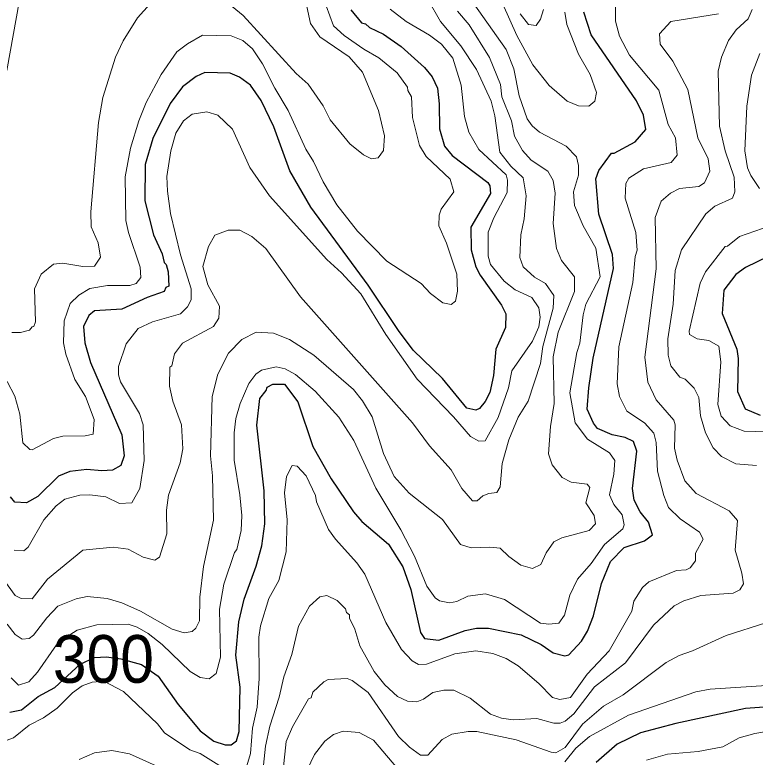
# Model space of a CAD drawing. Extents: x 673.3 to 698.5, y 6984.3 to 7012.3.
# Drawn here: x 687.627 to 688.869, y 6986.54 to 6987.786 of the extents above; entities that cross this region are included whole.
import ezdxf
from ezdxf.enums import TextEntityAlignment as Align

# ---------------------------------------------------------------- set-up
doc = ezdxf.new("R2010")
doc.units = 0
doc.header["$LTSCALE"] = 0.032
doc.layers.add('1', color=7, linetype='Continuous', lineweight=25)
doc.layers.add('2', color=7, linetype='Continuous', lineweight=13)
doc.layers.add('61', color=7, linetype='Continuous')

msp = doc.modelspace()

# ---------------------------------------------------------------- linework, layer by layer
at = {"layer": '1'}
for points in [[(688.1903, 6987.794), (688.2086, 6987.7726), (688.2153, 6987.7709), (688.2217, 6987.7647), (688.2455, 6987.7531), (688.2751, 6987.7325), (688.3143, 6987.6971), (688.3272, 6987.6818), (688.336, 6987.6625), (688.3389, 6987.6365), (688.3393, 6987.5944), (688.3478, 6987.5653), (688.3607, 6987.5499), (688.4207, 6987.5043), (688.4238, 6987.4986), (688.4252, 6987.4857), (688.3918, 6987.4293), (688.3926, 6987.3911), (688.4004, 6987.3627)], [(688.1014, 6987.1361), (688.1266, 6987.0612), (688.1577, 6987.0072), (688.1949, 6986.9515), (688.2088, 6986.9354), (688.2535, 6986.8971), (688.2781, 6986.8592), (688.2915, 6986.8211), (688.3076, 6986.7489), (688.3143, 6986.7388), (688.338, 6986.7362), (688.3823, 6986.7525), (688.4013, 6986.7564), (688.4214, 6986.7564), (688.4762, 6986.7451), (688.5101, 6986.7292), (688.5304, 6986.715), (688.5495, 6986.7101), (688.5564, 6986.7116), (688.5777, 6986.7346), (688.588, 6986.7513), (688.5979, 6986.7771), (688.6112, 6986.8312), (688.6264, 6986.868), (688.6492, 6986.8916), (688.6834, 6986.9031), (688.697, 6986.913), (688.6903, 6986.9345), (688.6764, 6986.9518), (688.6662, 6986.9714), (688.6631, 6986.991), (688.6704, 6987.0537), (688.6647, 6987.0696), (688.6511, 6987.0764), (688.6289, 6987.0809), (688.6044, 6987.0912), (688.5977, 6987.1004), (688.5873, 6987.124), (688.5897, 6987.1596), (688.5971, 6987.2096), (688.6312, 6987.3599), (688.6296, 6987.3836), (688.6068, 6987.4514), (688.602, 6987.5106), (688.607, 6987.5247), (688.628, 6987.5536), (688.6325, 6987.5538), (688.6678, 6987.5725), (688.6858, 6987.5931), (688.6818, 6987.6174), (688.6697, 6987.6414), (688.594, 6987.7522), (688.5816, 6987.7902)], [(688.4004, 6987.3627), (688.4075, 6987.3488), (688.4435, 6987.2987), (688.4509, 6987.284), (688.4503, 6987.2611), (688.4341, 6987.2245), (688.4301, 6987.1807), (688.4237, 6987.1517), (688.4162, 6987.1369), (688.4063, 6987.1252), (688.4006, 6987.1222), (688.3854, 6987.1254), (688.3443, 6987.1753), (688.295, 6987.223), (688.2705, 6987.2557), (688.2199, 6987.332), (688.1233, 6987.4631), (688.0882, 6987.5242), (688.0612, 6987.5977), (688.0399, 6987.642), (688.0221, 6987.6677), (688.0038, 6987.6813), (687.9879, 6987.6881), (687.9453, 6987.6888), (687.931, 6987.6824), (687.908, 6987.6651), (687.8871, 6987.6371), (687.8585, 6987.5784), (687.8455, 6987.5345), (687.8446, 6987.4736), (687.8596, 6987.4165), (687.8738, 6987.3846), (687.8771, 6987.3701), (687.8806, 6987.3666), (687.8838, 6987.3544), (687.8853, 6987.3303), (687.8803, 6987.3279), (687.8772, 6987.3214), (687.8488, 6987.3116), (687.8063, 6987.2916), (687.7601, 6987.289), (687.751, 6987.2809), (687.742, 6987.2626), (687.7444, 6987.2352), (687.7538, 6987.2023), (687.8064, 6987.0811), (687.8104, 6987.0456), (687.8047, 6987.0295), (687.7904, 6987.0217), (687.7728, 6987.0203), (687.7473, 6987.0227), (687.7191, 6987.0195), (687.6997, 6987.0113), (687.665, 6986.9776), (687.6465, 6986.9669), (687.6268, 6986.9681), (687.6194, 6986.9768)], [(688.9095, 6987.389), (688.8531, 6987.3617), (688.8364, 6987.35), (688.8168, 6987.3239), (688.8137, 6987.2845), (688.8382, 6987.2244), (688.8405, 6987.2087), (688.8396, 6987.1537), (688.8524, 6987.1244), (688.8773, 6987.114)], [(687.6184, 6986.6156), (687.6381, 6986.6192), (687.6657, 6986.6418), (687.6937, 6986.657), (687.7363, 6986.6961), (687.7604, 6986.7071), (687.7806, 6986.708), (687.8045, 6986.7047), (687.8394, 6986.6953), (687.8673, 6986.6758), (687.9006, 6986.628), (687.9379, 6986.5841), (687.9604, 6986.5666), (687.9795, 6986.5603), (687.9895, 6986.5608), (687.9985, 6986.567), (688.0034, 6986.5831), (688.005, 6986.6571), (687.9977, 6986.7109), (688.0025, 6986.7667), (688.0118, 6986.8052), (688.0319, 6986.8602), (688.0413, 6986.8944), (688.0465, 6986.9312), (688.0451, 6986.9871), (688.0329, 6987.097), (688.0379, 6987.1419), (688.0487, 6987.1554), (688.05, 6987.1611), (688.0598, 6987.1661), (688.0791, 6987.166), (688.1014, 6987.1361)], [(688.9306, 6986.6269), (688.8528, 6986.6213), (688.7358, 6986.5961), (688.6765, 6986.5804), (688.6376, 6986.5616), (688.6025, 6986.5306)]]:
    msp.add_lwpolyline(points, dxfattribs=at)
at = {"layer": '2'}
for points in [[(688.5645, 6987.4889), (688.5726, 6987.5164), (688.5726, 6987.5328), (688.5694, 6987.5475), (688.5522, 6987.5651), (688.5074, 6987.5887), (688.4949, 6987.5997), (688.4867, 6987.611), (688.4733, 6987.6499), (688.4643, 6987.6951), (688.4513, 6987.7278), (688.373, 6987.839)], [(687.6344, 6987.8112), (687.6132, 6987.6923)], [(687.6215, 6987.2525), (687.6364, 6987.2525), (687.6512, 6987.2564), (687.6556, 6987.262), (687.6587, 6987.2624), (687.6614, 6987.2704), (687.6597, 6987.326), (687.6707, 6987.3505), (687.6915, 6987.3671), (687.7073, 6987.3689), (687.7407, 6987.3635), (687.7604, 6987.364), (687.7704, 6987.3789), (687.7665, 6987.4033), (687.755, 6987.4297), (687.7542, 6987.4554), (687.7672, 6987.6048), (687.7746, 6987.6469), (687.7956, 6987.7148), (687.8084, 6987.7422), (687.8323, 6987.7809), (687.8595, 6987.8104)], [(687.6558, 6986.8056), (687.6814, 6986.8385), (687.7406, 6986.8875), (687.7915, 6986.8924), (687.8166, 6986.8892), (687.8423, 6986.8756), (687.8615, 6986.8706), (687.8697, 6986.8753), (687.882, 6986.9149), (687.8812, 6986.9543), (687.8843, 6986.9798), (687.9044, 6987.0337), (687.9088, 6987.0574), (687.9064, 6987.0977), (687.8917, 6987.1371), (687.8861, 6987.1626), (687.887, 6987.1942), (687.8901, 6987.1965), (687.8945, 6987.2166), (687.9083, 6987.2347), (687.9599, 6987.2628), (687.969, 6987.2769), (687.9699, 6987.2969), (687.9503, 6987.3325), (687.9423, 6987.3634), (687.9518, 6987.3968), (687.9625, 6987.4159), (687.9846, 6987.4242), (688.0045, 6987.4241), (688.0243, 6987.414), (688.048, 6987.3934), (688.1061, 6987.3125), (688.2942, 6987.1007), (688.3224, 6987.0621), (688.3592, 6987.0222), (688.3767, 6986.9909), (688.3945, 6986.9703), (688.4024, 6986.97), (688.4122, 6986.9787), (688.4222, 6986.9826), (688.4357, 6986.9838), (688.4414, 6986.9935), (688.4448, 6987.0328), (688.4556, 6987.0723), (688.4715, 6987.1104), (688.4882, 6987.1375), (688.5087, 6987.2008), (688.5126, 6987.2292), (688.5302, 6987.2932), (688.531, 6987.3149), (688.5171, 6987.3346), (688.4987, 6987.3452), (688.4797, 6987.3627), (688.4741, 6987.3782), (688.4756, 6987.4166), (688.4814, 6987.4431), (688.4846, 6987.4821), (688.4797, 6987.512), (688.459, 6987.532), (688.4407, 6987.5554), (688.4324, 6987.6163), (688.4262, 6987.6411), (688.4014, 6987.6941), (688.3751, 6987.7335), (688.341, 6987.7746), (688.319, 6987.8132)], [(687.973, 6987.8153), (688.0101, 6987.7847), (688.0989, 6987.6871), (688.119, 6987.6694), (688.1441, 6987.6329), (688.1561, 6987.6098), (688.1888, 6987.5693), (688.212, 6987.5506), (688.2251, 6987.544), (688.2364, 6987.5457), (688.2452, 6987.5582), (688.2468, 6987.5828), (688.237, 6987.6254), (688.2099, 6987.6895), (688.1875, 6987.715), (688.1385, 6987.7491), (688.1228, 6987.771), (688.1169, 6987.8)], [(688.6346, 6987.8064), (688.6346, 6987.7753), (688.6412, 6987.7498), (688.6583, 6987.718)], [(687.6138, 6987.1702), (687.6269, 6987.1455), (687.6353, 6987.1154), (687.6402, 6987.0673), (687.6518, 6987.0561), (687.6556, 6987.0555), (687.6914, 6987.0748), (687.7071, 6987.0788), (687.7446, 6987.079), (687.7581, 6987.0822), (687.7598, 6987.1063), (687.7451, 6987.1452), (687.7275, 6987.1737), (687.712, 6987.216), (687.7086, 6987.2355), (687.7094, 6987.2722), (687.7193, 6987.3013), (687.734, 6987.3153), (687.7528, 6987.3262), (687.7821, 6987.3313), (687.8198, 6987.3314), (687.8305, 6987.3347), (687.838, 6987.345), (687.8372, 6987.362), (687.8173, 6987.4202), (687.8128, 6987.4407), (687.812, 6987.5136), (687.8209, 6987.5619), (687.8349, 6987.6081), (687.8472, 6987.6385), (687.8722, 6987.6856), (687.8988, 6987.7236), (687.9167, 6987.7373), (687.9418, 6987.7516), (687.9895, 6987.7508), (688.0091, 6987.7426), (688.0255, 6987.7286), (688.0424, 6987.7035), (688.063, 6987.6626), (688.0856, 6987.6254), (688.1148, 6987.5605), (688.1278, 6987.5394), (688.1439, 6987.5055), (688.1672, 6987.4667), (688.2015, 6987.4228), (688.2507, 6987.3725), (688.3085, 6987.3348), (688.3245, 6987.3181), (688.3448, 6987.3022), (688.359, 6987.2997), (688.3664, 6987.3054), (688.3698, 6987.3222), (688.3682, 6987.3504), (688.3509, 6987.4025), (688.3381, 6987.4317), (688.3389, 6987.4495), (688.3424, 6987.4598), (688.3633, 6987.4888), (688.3571, 6987.5099), (688.3171, 6987.5479), (688.3056, 6987.5664), (688.2941, 6987.6134), (688.2924, 6987.6482), (688.286, 6987.6589), (688.2858, 6987.6645), (688.2682, 6987.6887), (688.2377, 6987.7135), (688.2121, 6987.7279), (688.1791, 6987.7513), (688.1617, 6987.7671), (688.1493, 6987.8007)], [(688.2564, 6987.7951), (688.2837, 6987.7746), (688.3227, 6987.7515), (688.3427, 6987.7363), (688.3616, 6987.7133), (688.3755, 6987.6677), (688.3813, 6987.615), (688.3888, 6987.589), (688.4055, 6987.5595), (688.4514, 6987.5173), (688.4537, 6987.5081), (688.4527, 6987.4877), (688.4304, 6987.4452), (688.4213, 6987.4208), (688.4208, 6987.3805), (688.4251, 6987.3668), (688.4477, 6987.3385), (688.4661, 6987.3242), (688.4945, 6987.3116), (688.506, 6987.2942), (688.5082, 6987.2783), (688.5058, 6987.2623), (688.4954, 6987.238), (688.4609, 6987.1881), (688.4553, 6987.1597), (688.4378, 6987.1101), (688.4161, 6987.0709), (688.4051, 6987.07), (688.3912, 6987.078), (688.3629, 6987.1111), (688.3018, 6987.174), (688.2493, 6987.2491), (688.2071, 6987.3173), (688.1748, 6987.3529), (688.1504, 6987.3749), (688.054, 6987.4819), (688.0212, 6987.5296), (687.992, 6987.5937), (687.9672, 6987.6173), (687.9491, 6987.6228), (687.9244, 6987.6188), (687.9096, 6987.6081), (687.8971, 6987.5874), (687.8883, 6987.5576), (687.882, 6987.5143), (687.8827, 6987.4896), (687.8878, 6987.4525), (687.9048, 6987.3828), (687.9227, 6987.3257), (687.9227, 6987.3073), (687.9164, 6987.2956), (687.9047, 6987.2837), (687.8578, 6987.2703), (687.8336, 6987.2594), (687.8135, 6987.2335)], [(688.4458, 6987.8034), (688.469, 6987.751), (688.4962, 6987.7017), (688.5233, 6987.6673), (688.5534, 6987.641), (688.5724, 6987.6332), (688.5899, 6987.6323), (688.6003, 6987.6409), (688.6027, 6987.6552), (688.592, 6987.6859), (688.5726, 6987.7198), (688.5532, 6987.7697), (688.5498, 6987.7903)], [(688.5139, 6987.7946), (688.5091, 6987.7787), (688.5017, 6987.7678), (688.4887, 6987.7697), (688.4747, 6987.7877)], [(688.8641, 6987.7946), (688.8575, 6987.7792), (688.8373, 6987.7605), (688.8243, 6987.7426), (688.8128, 6987.7148), (688.8072, 6987.6915), (688.8094, 6987.5987), (688.819, 6987.5573), (688.834, 6987.5133), (688.835, 6987.4885), (688.8312, 6987.4779), (688.8012, 6987.4644), (688.7861, 6987.452), (688.7454, 6987.3911), (688.7347, 6987.3569), (688.7315, 6987.2999), (688.7225, 6987.242), (688.7233, 6987.2143), (688.7275, 6987.1968), (688.7428, 6987.1777), (688.7519, 6987.1742), (688.7667, 6987.1591), (688.7744, 6987.1436), (688.7775, 6987.1128), (688.7857, 6987.0844), (688.7987, 6987.0591), (688.8125, 6987.0444), (688.8367, 6987.0322), (688.8713, 6987.0293)], [(688.1029, 6986.7595), (688.1214, 6986.7931), (688.1386, 6986.8092), (688.1504, 6986.8111), (688.1679, 6986.8029), (688.1816, 6986.789), (688.1834, 6986.7827), (688.1882, 6986.779), (688.1883, 6986.773), (688.1975, 6986.7546), (688.2059, 6986.7269), (688.2296, 6986.6838), (688.2478, 6986.661), (688.2691, 6986.6418), (688.2859, 6986.6338), (688.3013, 6986.6325), (688.3124, 6986.637), (688.3281, 6986.6482), (688.3468, 6986.6523), (688.3635, 6986.6523), (688.391, 6986.6389), (688.4247, 6986.6122), (688.4433, 6986.6051), (688.4629, 6986.6026), (688.5026, 6986.6049), (688.5313, 6986.597), (688.5421, 6986.5969), (688.5503, 6986.6004), (688.5648, 6986.6128), (688.5997, 6986.6581), (688.6513, 6986.6983), (688.6984, 6986.7616), (688.7332, 6986.794), (688.7496, 6986.8021), (688.7778, 6986.811), (688.8323, 6986.8149), (688.8434, 6986.8206), (688.8494, 6986.8305), (688.847, 6986.8488), (688.8357, 6986.8874), (688.8397, 6986.9369), (688.8253, 6986.9531), (688.7702, 6986.9825), (688.7509, 6987.0036), (688.7381, 6987.0384), (688.7339, 6987.0584), (688.7346, 6987.0977), (688.7324, 6987.1053), (688.7027, 6987.1396), (688.6891, 6987.1694), (688.6842, 6987.2111), (688.7029, 6987.3593), (688.7013, 6987.4454), (688.7111, 6987.473), (688.727, 6987.4864), (688.742, 6987.4942), (688.7746, 6987.4974), (688.7842, 6987.5039), (688.7933, 6987.5233), (688.79, 6987.5439), (688.773, 6987.5792), (688.7564, 6987.6602), (688.731, 6987.7079), (688.7095, 6987.7364), (688.7087, 6987.7541), (688.7276, 6987.7744), (688.8074, 6987.7876)], [(688.3695, 6987.792), (688.3892, 6987.769), (688.4233, 6987.7139), (688.442, 6987.6687), (688.444, 6987.648), (688.46, 6987.6081), (688.4652, 6987.5823), (688.4787, 6987.5578), (688.4931, 6987.542), (688.5212, 6987.5235), (688.5302, 6987.5078), (688.5336, 6987.4863), (688.5303, 6987.4355), (688.5357, 6987.3935), (688.544, 6987.3734), (688.5658, 6987.3462), (688.5657, 6987.3215), (688.5386, 6987.253), (688.5303, 6987.212), (688.5318, 6987.1335), (688.5254, 6987.095), (688.5225, 6987.0492), (688.5284, 6987.0305), (688.545, 6987.0095), (688.5602, 6987.0015), (688.587, 6986.9983), (688.5918, 6986.9923), (688.5849, 6986.9667), (688.5992, 6986.9457), (688.6009, 6986.9314), (688.5908, 6986.9205), (688.5444, 6986.9079), (688.5312, 6986.9014), (688.5181, 6986.8826), (688.5097, 6986.863), (688.4952, 6986.8567), (688.4758, 6986.862), (688.4557, 6986.8765), (688.4412, 6986.8908), (688.4237, 6986.8925), (688.3926, 6986.8909), (688.3747, 6986.8969), (688.3445, 6986.9388), (688.2887, 6986.9829), (688.2633, 6987.0111), (688.2456, 6987.0496), (688.2263, 6987.111), (688.2103, 6987.1379), (688.1951, 6987.1568)], [(688.6583, 6987.718), (688.7074, 6987.6592), (688.7232, 6987.6016), (688.7356, 6987.5792), (688.7385, 6987.5504), (688.7284, 6987.5378), (688.6815, 6987.5275), (688.6572, 6987.5117), (688.652, 6987.5024), (688.6508, 6987.4782), (688.6687, 6987.4202), (688.671, 6987.3906), (688.6677, 6987.3801), (688.6637, 6987.3366), (688.6403, 6987.2286), (688.6373, 6987.1665), (688.6417, 6987.1452), (688.6539, 6987.1207), (688.6832, 6987.1011), (688.6992, 6987.0837), (688.703, 6987.0681), (688.7053, 6987.0198), (688.7156, 6986.9791), (688.7237, 6986.959), (688.7434, 6986.9398), (688.7758, 6986.9172), (688.782, 6986.9055), (688.7689, 6986.8823), (688.7688, 6986.8692), (688.76, 6986.8575), (688.7534, 6986.8542), (688.7372, 6986.8533), (688.6905, 6986.8341), (688.6802, 6986.8247), (688.6656, 6986.8015), (688.662, 6986.7847), (688.6239, 6986.7183), (688.587, 6986.6792), (688.5592, 6986.6397), (688.5415, 6986.6368), (688.5289, 6986.64), (688.5058, 6986.6636), (688.4714, 6986.6931), (688.451, 6986.7053), (688.4291, 6986.7141), (688.4006, 6986.7181), (688.3651, 6986.7133), (688.3175, 6986.696), (688.3041, 6986.6954), (688.2936, 6986.7017), (688.2755, 6986.7207), (688.2492, 6986.7657), (688.2141, 6986.8471), (688.2006, 6986.8662), (688.1646, 6986.9055), (688.1532, 6986.9218), (688.1331, 6986.9685), (688.1311, 6986.9791), (688.1155, 6987.0122), (688.1007, 6987.028), (688.0923, 6987.0291), (688.0826, 6987.0108), (688.0791, 6986.9837), (688.0839, 6986.9383), (688.0823, 6986.8843), (688.0697, 6986.8364), (688.0532, 6986.8064), (688.0391, 6986.7603), (688.036, 6986.7413), (688.0368, 6986.6716), (688.0334, 6986.6238), (688.0254, 6986.5885), (688.022, 6986.5458), (688.0159, 6986.5252)], [(688.8763, 6987.4941), (688.8617, 6987.5161), (688.8565, 6987.5287), (688.852, 6987.5577), (688.8553, 6987.6322), (688.8631, 6987.6847), (688.877, 6987.7209)], [(687.6203, 6986.6732), (687.6329, 6986.6605), (687.6501, 6986.6663), (687.6649, 6986.6826), (687.6968, 6986.7284), (687.7067, 6986.7375), (687.7311, 6986.753), (687.7641, 6986.7621), (687.8169, 6986.7629), (687.8321, 6986.7578), (687.8503, 6986.7475), (687.874, 6986.729), (687.9211, 6986.6834), (687.9377, 6986.6733), (687.953, 6986.6712), (687.9644, 6986.6803), (687.9716, 6986.7079), (687.97, 6986.7885), (687.9776, 6986.8303), (687.9952, 6986.8833), (687.9994, 6986.8882), (688.0067, 6986.9204), (688.0074, 6986.9452), (688.0042, 6986.9802), (687.9945, 6987.0384), (687.9945, 6987.084), (687.9977, 6987.108), (688.0048, 6987.1332), (688.0193, 6987.1672), (688.0314, 6987.1828), (688.0404, 6987.1896), (688.065, 6987.1952), (688.0805, 6987.1914), (688.0978, 6987.1821), (688.1309, 6987.1542), (688.1705, 6987.1105), (688.1958, 6987.0711), (688.2323, 6986.9916), (688.2744, 6986.9212), (688.2976, 6986.8773), (688.3182, 6986.8271), (688.3323, 6986.807), (688.3391, 6986.802), (688.356, 6986.7989), (688.3686, 6986.8013), (688.3868, 6986.8101), (688.4163, 6986.8142), (688.4483, 6986.8047), (688.5091, 6986.7647), (688.5231, 6986.763), (688.5399, 6986.7646), (688.5494, 6986.7781), (688.5583, 6986.8119), (688.5709, 6986.8385), (688.5939, 6986.8651), (688.6161, 6986.8969), (688.6468, 6986.923), (688.6491, 6986.9299), (688.646, 6986.9465), (688.6321, 6986.9639), (688.6248, 6986.9802), (688.6321, 6987.0149), (688.6336, 6987.0379), (688.6247, 6987.0505), (688.5877, 6987.0737), (688.567, 6987.1007), (688.558, 6987.1512), (688.5697, 6987.2188), (688.5751, 6987.2348), (688.5806, 6987.2824), (688.5849, 6987.2999), (688.6091, 6987.3462), (688.6018, 6987.3944), (688.5806, 6987.4319), (688.5657, 6987.4655), (688.5645, 6987.4889)], [(688.9087, 6987.0855), (688.8505, 6987.0871), (688.8271, 6987.0959), (688.8121, 6987.1123), (688.8064, 6987.1317), (688.8113, 6987.2031), (688.8081, 6987.2297), (688.7915, 6987.2391), (688.7716, 6987.2418), (688.7592, 6987.2492), (688.7584, 6987.2549), (688.7769, 6987.3352), (688.7856, 6987.3545), (688.8185, 6987.3971), (688.8226, 6987.3975), (688.8428, 6987.4135), (688.8941, 6987.4318)], [(688.1951, 6987.1568), (688.1282, 6987.2147), (688.0875, 6987.2409), (688.061, 6987.2515), (688.0319, 6987.2532), (688.0079, 6987.2407), (687.9853, 6987.218), (687.9674, 6987.1826), (687.9581, 6987.145), (687.9553, 6987.0456), (687.9585, 6987.0119), (687.9601, 6986.9375), (687.9431, 6986.8599), (687.9374, 6986.8086), (687.9365, 6986.7687), (687.9306, 6986.7562), (687.9242, 6986.7506), (687.911, 6986.7487), (687.8908, 6986.7547), (687.8377, 6986.785), (687.8063, 6986.799), (687.7818, 6986.8061), (687.748, 6986.8093), (687.7295, 6986.8055), (687.6989, 6986.7931), (687.6802, 6986.7737), (687.6581, 6986.7444), (687.651, 6986.7391), (687.6389, 6986.7379), (687.6271, 6986.7459), (687.6138, 6986.763)], [(687.8135, 6987.2335), (687.8006, 6987.1957), (687.8006, 6987.1816), (687.8038, 6987.1696), (687.8359, 6987.1167), (687.8421, 6987.0977), (687.8438, 6987.0377), (687.8362, 6986.9909), (687.8233, 6986.9666), (687.8025, 6986.9658), (687.7796, 6986.9765), (687.7523, 6986.9804), (687.7357, 6986.9796), (687.7108, 6986.9728), (687.6963, 6986.9616), (687.6753, 6986.9382), (687.6491, 6986.8925), (687.6416, 6986.886), (687.6256, 6986.887)], [(687.586, 6986.8675), (687.627, 6986.8112), (687.6373, 6986.8062), (687.6558, 6986.8056)], [(688.0414, 6986.4997), (688.0473, 6986.5585), (688.0544, 6986.5918), (688.0702, 6986.6403), (688.078, 6986.6749), (688.0914, 6986.7119), (688.1029, 6986.7595)], [(688.8868, 6986.7654), (688.8202, 6986.7442), (688.7642, 6986.7183), (688.7418, 6986.7107), (688.7195, 6986.6988), (688.6475, 6986.6446), (688.6148, 6986.6252), (688.5795, 6986.595), (688.55, 6986.5562), (688.5347, 6986.5472), (688.5268, 6986.548), (688.4681, 6986.5692), (688.4022, 6986.5828), (688.3873, 6986.583), (688.36, 6986.5785), (688.3441, 6986.5695), (688.3198, 6986.5434), (688.3072, 6986.5431), (688.2889, 6986.5565), (688.2704, 6986.5743), (688.2195, 6986.6485), (688.1926, 6986.6687), (688.1844, 6986.6718), (688.1525, 6986.6701), (688.1451, 6986.6665), (688.1267, 6986.6492), (688.124, 6986.6394), (688.1196, 6986.6378), (688.0926, 6986.5906), (688.0823, 6986.5664), (688.0709, 6986.4603)], [(687.9827, 6986.5178), (687.9377, 6986.5462), (687.9206, 6986.5523), (687.8776, 6986.5808), (687.8659, 6986.5958), (687.8092, 6986.6502), (687.776, 6986.6672), (687.7565, 6986.6657), (687.7396, 6986.6596), (687.7235, 6986.6479), (687.6979, 6986.6223), (687.6746, 6986.6059), (687.6507, 6986.5935), (687.6245, 6986.5722), (687.5963, 6986.562), (687.5854, 6986.5705), (687.5679, 6986.6362), (687.5538, 6986.6523), (687.5397, 6986.6636), (687.5067, 6986.6694), (687.4588, 6986.6604), (687.441, 6986.662), (687.4194, 6986.6676)], [(688.5498, 6986.5319), (688.5682, 6986.555), (688.5909, 6986.5745), (688.6565, 6986.6106), (688.7697, 6986.6497), (688.7935, 6986.6538), (688.8884, 6986.6603)], [(688.9902, 6986.6002), (688.8688, 6986.5797), (688.8424, 6986.5725), (688.8147, 6986.557), (688.7735, 6986.5496), (688.7219, 6986.5449), (688.6866, 6986.5349)], [(688.1171, 6986.5186), (688.1297, 6986.5442), (688.1467, 6986.5668), (688.1614, 6986.5776), (688.1775, 6986.5835), (688.2045, 6986.5813), (688.2287, 6986.5685), (688.2852, 6986.5018)], [(687.7344, 6986.536), (687.7602, 6986.5472), (687.7892, 6986.5512), (687.8191, 6986.5453), (687.8636, 6986.5254)]]:
    msp.add_lwpolyline(points, dxfattribs=at)

# ---------------------------------------------------------------- texts
at = {"layer": '61', "width": 0.95}
msp.add_text('300', height=0.08, dxfattribs=at).set_placement((687.7753, 6986.6647), align=Align.CENTER)

doc.saveas('drawing.dxf')
